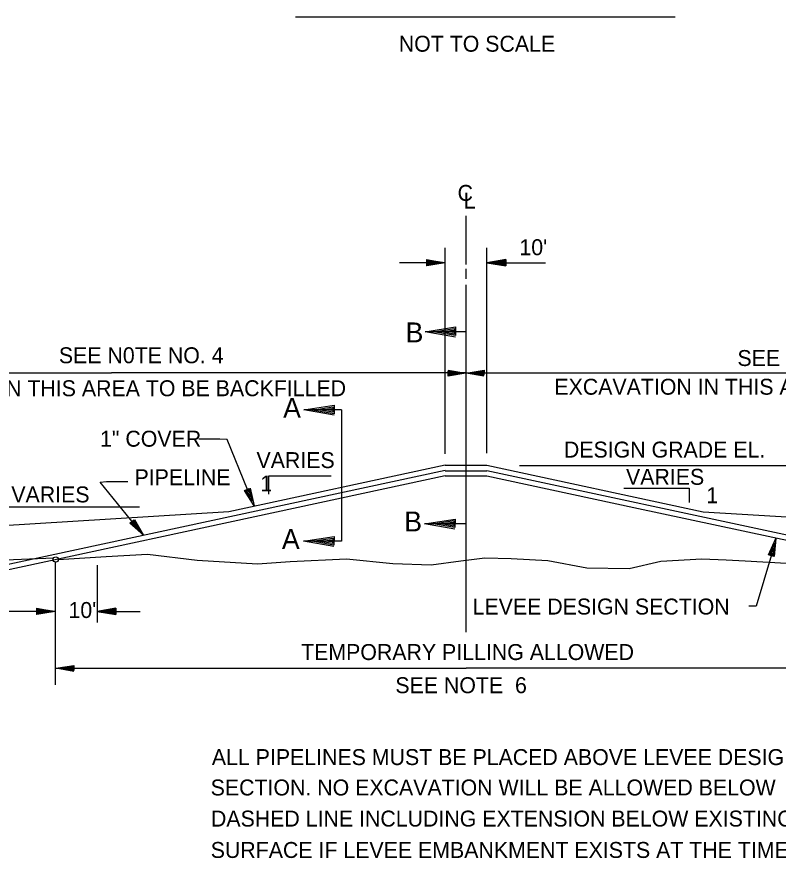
# Model space of a CAD drawing. Extents: x 2127959 to 2137375, y 2146193 to 2153470.
# Drawn here: x 2130277 to 2131850, y 2149874 to 2151610 of the extents above; entities that cross this region are included whole.
import ezdxf

# ---------------------------------------------------------------- set-up
doc = ezdxf.new("R2010")
doc.units = 0
for name, color, linetype in [('Level 1', 7, 'Continuous'), ('Level 3', 7, 'Continuous'), ('Level 5', 7, 'Continuous'), ('Level 50', 7, 'Continuous'), ('Level 63', 7, 'Continuous')]:
    doc.layers.add(name, color=color, linetype=linetype)

msp = doc.modelspace()

# ---------------------------------------------------------------- linework, layer by layer
at = {"layer": 'Level 1'}
for p, q in [((2131205.402, 2151099.111), (2131205.402, 2151199.222)), ((2131205.402, 2151069.227), (2131205.402, 2151090.146)), ((2131205.402, 2150960.045), (2131205.402, 2151057.274)), ((2131162.204, 2150684.43), (2130715.397, 2150588.688)), ((2131162.204, 2150684.43), (2131248.601, 2150684.444)), ((2131248.601, 2150684.444), (2131695.4, 2150588.688)), ((2131162.301, 2150662.426), (2130858.58, 2150597.329)), ((2131162.301, 2150662.426), (2131248.501, 2150662.426)), ((2131248.501, 2150662.426), (2131551.79, 2150597.432)), ((2130715.396, 2150588.701), (2130170.987, 2150554.673)), ((2131695.401, 2150588.702), (2132239.818, 2150554.673)), ((2131836.343, 2150499.825), (2131804.74, 2150393.885)), ((2131804.74, 2150393.885), (2131789.466, 2150393.885))]:
    msp.add_line(p, q, dxfattribs=at)
at = {"layer": 'Level 3'}
for p, q in [((2131162.301, 2150708.371), (2131162.301, 2151133.477)), ((2131248.501, 2150709.475), (2131248.501, 2151133.477)), ((2131123.544, 2151109.078), (2131123.544, 2151096.147)), ((2131123.544, 2151109.078), (2131162.301, 2151102.613)), ((2131287.257, 2151109.078), (2131248.501, 2151102.613)), ((2131286.447, 2151108.283), (2131255.05, 2151103.058)), ((2131286.516, 2151103.526), (2131286.447, 2151108.283)), ((2131287.257, 2151109.078), (2131287.257, 2151096.147)), ((2131162.301, 2151102.613), (2131067.803, 2151102.613)), ((2131162.301, 2151102.613), (2131123.544, 2151102.613)), ((2131162.301, 2151102.613), (2131123.544, 2151096.147)), ((2131124.112, 2151096.94), (2131156.526, 2151102.13)), ((2131124.285, 2151101.975), (2131124.112, 2151096.94)), ((2131124.322, 2151107.938), (2131124.25, 2151103.163)), ((2131124.25, 2151103.163), (2131156.573, 2151103.027)), ((2131156.526, 2151102.13), (2131125.061, 2151101.989)), ((2131125.061, 2151101.989), (2131125.061, 2151097.852)), ((2131125.061, 2151097.852), (2131149.094, 2151101.454)), ((2131125.129, 2151108.009), (2131125.11, 2151103.749)), ((2131125.11, 2151103.749), (2131149.317, 2151103.576)), ((2131156.573, 2151103.027), (2131125.129, 2151108.009)), ((2131149.094, 2151101.454), (2131125.887, 2151101.13)), ((2131125.887, 2151101.13), (2131125.957, 2151098.735)), ((2131125.957, 2151098.735), (2131138.626, 2151100.437)), ((2131149.317, 2151103.576), (2131125.974, 2151107.043)), ((2131125.974, 2151107.043), (2131125.974, 2151104.663)), ((2131125.974, 2151104.663), (2131138.456, 2151104.455)), ((2131138.626, 2151100.437), (2131126.856, 2151100.51)), ((2131126.856, 2151100.51), (2131126.87, 2151099.542)), ((2131126.87, 2151099.542), (2131130.457, 2151099.836)), ((2131138.456, 2151104.455), (2131126.905, 2151106.298)), ((2131126.905, 2151106.298), (2131126.925, 2151105.333)), ((2131126.925, 2151105.333), (2131130.595, 2151105.233)), ((2131248.501, 2151102.613), (2131369.198, 2151102.613)), ((2131248.501, 2151102.613), (2131287.257, 2151102.613)), ((2131248.501, 2151102.613), (2131287.257, 2151096.147)), ((2131255.05, 2151103.058), (2131285.843, 2151103.423)), ((2131286.619, 2151097.025), (2131255.155, 2151102.01)), ((2131255.155, 2151102.01), (2131285.775, 2151102.01)), ((2131285.775, 2151107.474), (2131261.294, 2151103.54)), ((2131261.294, 2151103.54), (2131284.912, 2151104.179)), ((2131285.874, 2151097.82), (2131261.448, 2151101.524)), ((2131261.448, 2151101.524), (2131285.014, 2151101.285)), ((2131284.842, 2151106.529), (2131270.551, 2151104.373)), ((2131270.551, 2151104.373), (2131284.14, 2151104.611)), ((2131284.999, 2151098.713), (2131270.723, 2151100.784)), ((2131270.723, 2151100.784), (2131284.221, 2151100.558)), ((2131284.186, 2151105.784), (2131280.086, 2151105.165)), ((2131284.396, 2151099.423), (2131280.086, 2151099.992)), ((2131284.14, 2151104.611), (2131284.186, 2151105.784)), ((2131284.221, 2151100.558), (2131284.396, 2151099.423)), ((2131284.912, 2151104.179), (2131284.842, 2151106.529)), ((2131285.014, 2151101.285), (2131284.999, 2151098.713)), ((2131285.843, 2151103.423), (2131285.775, 2151107.474)), ((2131285.775, 2151102.01), (2131285.874, 2151097.82)), ((2131286.549, 2151101.989), (2131286.619, 2151097.025)), ((2131205.402, 2150339.898), (2131205.402, 2150925.907)), ((2129739.982, 2150875.068), (2130472.692, 2150875.068)), ((2129739.982, 2150875.068), (2130472.692, 2150875.068)), ((2129739.982, 2150875.068), (2130472.692, 2150875.068)), ((2131205.402, 2150875.068), (2130472.692, 2150875.068)), ((2131205.402, 2150875.068), (2130472.692, 2150875.068)), ((2131205.402, 2150875.068), (2130472.692, 2150875.068)), ((2131205.402, 2150875.068), (2131938.111, 2150875.068)), ((2131315.548, 2150683.978), (2131882.694, 2150683.978)), ((2131162.246, 2150673.424), (2129904.058, 2150403.823)), ((2130797.338, 2150661.771), (2130797.338, 2150624.655)), ((2130926.694, 2150661.771), (2130797.338, 2150661.771)), ((2131162.301, 2150673.203), (2131248.501, 2150673.203)), ((2131248.552, 2150673.424), (2132506.745, 2150403.823)), ((2131531.04, 2150636.975), (2131666.068, 2150636.975)), ((2131666.068, 2150636.975), (2131666.068, 2150607.649)), ((2130858.58, 2150597.329), (2129904.058, 2150392.79)), ((2130531.142, 2150597.738), (2130255.802, 2150597.738)), ((2131551.79, 2150597.432), (2132506.745, 2150392.79)), ((2130356.891, 2150484.697), (2130356.891, 2150231.059)), ((2130443.093, 2150478.437), (2130443.093, 2150360.256)), ((2130356.891, 2150382.98), (2130210.728, 2150382.98)), ((2130318.142, 2150389.445), (2130318.142, 2150376.517)), ((2130318.142, 2150389.445), (2130356.891, 2150382.98)), ((2130356.891, 2150382.98), (2130318.142, 2150382.98)), ((2130356.891, 2150382.98), (2130318.142, 2150376.517)), ((2130318.701, 2150377.31), (2130351.114, 2150382.495)), ((2130318.87, 2150382.343), (2130318.701, 2150377.31)), ((2130318.907, 2150388.308), (2130318.848, 2150383.531)), ((2130318.848, 2150383.531), (2130351.162, 2150383.394)), ((2130319.66, 2150382.363), (2130319.653, 2150378.222)), ((2130319.653, 2150378.222), (2130343.697, 2150381.825)), ((2130351.114, 2150382.495), (2130319.66, 2150382.363)), ((2130319.724, 2150388.359), (2130319.707, 2150384.119)), ((2130319.707, 2150384.119), (2130343.911, 2150383.946)), ((2130351.162, 2150383.394), (2130319.724, 2150388.359)), ((2130343.697, 2150381.825), (2130320.477, 2150381.498)), ((2130320.477, 2150381.498), (2130320.553, 2150379.099)), ((2130320.553, 2150379.099), (2130333.225, 2150380.807)), ((2130343.911, 2150383.946), (2130320.564, 2150387.407)), ((2130320.564, 2150387.407), (2130320.564, 2150385.032)), ((2130320.564, 2150385.032), (2130333.055, 2150384.824)), ((2130333.225, 2150380.807), (2130321.453, 2150380.873)), ((2130321.453, 2150380.873), (2130321.466, 2150379.912)), ((2130321.466, 2150379.912), (2130325.053, 2150380.207)), ((2130333.055, 2150384.824), (2130321.496, 2150386.671)), ((2130321.496, 2150386.671), (2130321.526, 2150385.704)), ((2130321.526, 2150385.704), (2130325.186, 2150385.598)), ((2130481.842, 2150389.445), (2130443.093, 2150382.98)), ((2130443.093, 2150382.98), (2130532.498, 2150382.98)), ((2130443.093, 2150382.98), (2130481.842, 2150382.98)), ((2130443.093, 2150382.98), (2130481.842, 2150376.517)), ((2130481.039, 2150388.652), (2130449.639, 2150383.428)), ((2130449.639, 2150383.428), (2130480.429, 2150383.787)), ((2130481.215, 2150377.393), (2130449.747, 2150382.375)), ((2130449.747, 2150382.375), (2130480.37, 2150382.375)), ((2130480.37, 2150387.84), (2130455.875, 2150383.912)), ((2130455.875, 2150383.912), (2130479.505, 2150384.55)), ((2130480.469, 2150378.185), (2130456.036, 2150381.894)), ((2130456.036, 2150381.894), (2130479.603, 2150381.652)), ((2130479.436, 2150386.892), (2130465.135, 2150384.737)), ((2130465.135, 2150384.737), (2130478.722, 2150384.978)), ((2130479.588, 2150379.085), (2130465.322, 2150381.152)), ((2130465.322, 2150381.152), (2130478.817, 2150380.929)), ((2130478.99, 2150379.79), (2130474.674, 2150380.358)), ((2130478.782, 2150386.15), (2130474.681, 2150385.531)), ((2130478.722, 2150384.978), (2130478.782, 2150386.15)), ((2130478.817, 2150380.929), (2130478.99, 2150379.79)), ((2130479.505, 2150384.55), (2130479.436, 2150386.892)), ((2130479.603, 2150381.652), (2130479.588, 2150379.085)), ((2130480.429, 2150383.787), (2130480.37, 2150387.84)), ((2130480.37, 2150382.375), (2130480.469, 2150378.185)), ((2130481.107, 2150383.891), (2130481.039, 2150388.652)), ((2130481.15, 2150382.363), (2130481.215, 2150377.393)), ((2130481.842, 2150389.445), (2130481.842, 2150376.517)), ((2130356.891, 2150265.559), (2131205.781, 2150265.559)), ((2132054.671, 2150265.559), (2131205.781, 2150265.559))]:
    msp.add_line(p, q, dxfattribs=at)
for points in [[(2130754.087, 2150634.384), (2130711.692, 2150738.053), (2130696.985, 2150738.193), (2130653.196, 2150738.193)], [(2130538.981, 2150539.867), (2130449.295, 2150649.89), (2130462.838, 2150650.805), (2130506.627, 2150650.805)]]:
    msp.add_lwpolyline(points, dxfattribs=at)
msp.add_circle((2130357.753, 2150490.025), 5.388, dxfattribs=at)
at = {"layer": 'Level 5'}
for p, q in [((2130462.183, 2150496.161), (2130547.229, 2150501.301)), ((2130547.229, 2150501.301), (2130649.852, 2150488.438)), ((2130218.267, 2150487.938), (2130286.98, 2150490.803)), ((2130286.98, 2150490.803), (2130353.592, 2150493.438)), ((2130363.138, 2150490.024), (2130462.183, 2150496.161)), ((2130649.852, 2150488.438), (2130774.81, 2150481.147)), ((2130774.81, 2150481.147), (2130842.269, 2150485.748)), ((2130842.269, 2150485.748), (2130958.59, 2150491.283)), ((2130958.59, 2150491.283), (2131053.789, 2150481.54)), ((2131133.25, 2150478.712), (2131194.798, 2150487.231)), ((2131194.798, 2150487.231), (2131243.999, 2150493.714)), ((2131243.999, 2150493.714), (2131298.446, 2150492.368)), ((2131298.446, 2150492.368), (2131374.01, 2150488.042)), ((2131374.01, 2150488.042), (2131455.175, 2150473.025)), ((2131542.239, 2150471.405), (2131608.012, 2150486.42)), ((2131608.012, 2150486.42), (2131692.556, 2150491.144)), ((2131692.556, 2150491.144), (2131742.605, 2150489.127)), ((2131742.605, 2150489.127), (2131781.825, 2150487.367)), ((2131781.825, 2150487.367), (2131867.045, 2150482.766)), ((2131053.789, 2150481.54), (2131133.25, 2150478.712)), ((2131455.175, 2150473.025), (2131542.239, 2150471.405))]:
    msp.add_line(p, q, dxfattribs=at)
at = {"layer": 'Level 50'}
for p, q in [((2131120.956, 2150960.045), (2131120.956, 2150960.045)), ((2131138.423, 2150959.906), (2131138.423, 2150959.906)), ((2131194.843, 2150874.633), (2131194.843, 2150874.633)), ((2131205.127, 2150874.551), (2131205.127, 2150874.551)), ((2131205.453, 2150874.91), (2131205.453, 2150874.91)), ((2131215.733, 2150874.831), (2131215.733, 2150874.831)), ((2130870.25, 2150798.66), (2130870.25, 2150798.66)), ((2130887.717, 2150798.521), (2130887.717, 2150798.521)), ((2130763.872, 2150610.314), (2130763.872, 2150610.314)), ((2130767.822, 2150600.811), (2130767.822, 2150600.811)), ((2131119.749, 2150563.657), (2131119.749, 2150563.657)), ((2131137.216, 2150563.518), (2131137.216, 2150563.518)), ((2130532.445, 2150548.031), (2130532.445, 2150548.031)), ((2130538.883, 2150539.992), (2130538.883, 2150539.992)), ((2130869.734, 2150527.678), (2130869.734, 2150527.678)), ((2130887.201, 2150527.539), (2130887.201, 2150527.539)), ((2131842.755, 2150523.532), (2131842.755, 2150523.532)), ((2131845.5, 2150533.434), (2131845.5, 2150533.434)), ((2130358.062, 2150265.578), (2130358.062, 2150265.578)), ((2130368.344, 2150265.498), (2130368.344, 2150265.498))]:
    msp.add_line(p, q, dxfattribs=at)
for points in [[(2131183.697, 2150949.183), (2131120.956, 2150960.045), (2131183.824, 2150970.009), (2131183.701, 2150952.216), (2131138.423, 2150959.906), (2131181.101, 2150966.665), (2131181.04, 2150955.24), (2131155.212, 2150959.783), (2131178.401, 2150963.324), (2131178.375, 2150958.633), (2131172.68, 2150959.671)], [(2131168.191, 2150880.948), (2131205.127, 2150874.551), (2131168.114, 2150868.685), (2131168.185, 2150879.161), (2131194.843, 2150874.633), (2131169.717, 2150870.652), (2131169.755, 2150877.381), (2131184.96, 2150874.706), (2131171.31, 2150872.618), (2131171.324, 2150875.384), (2131174.676, 2150874.772)], [(2131242.388, 2150868.513), (2131205.453, 2150874.91), (2131242.463, 2150880.776), (2131242.389, 2150870.301), (2131215.733, 2150874.831), (2131240.861, 2150878.809), (2131240.824, 2150872.079), (2131225.616, 2150874.755), (2131239.267, 2150876.844), (2131239.254, 2150874.079), (2131235.904, 2150874.688)], [(2130932.991, 2150787.798), (2130870.25, 2150798.66), (2130933.118, 2150808.624), (2130932.995, 2150790.831), (2130887.717, 2150798.521), (2130930.395, 2150805.28), (2130930.334, 2150793.855), (2130904.506, 2150798.398), (2130927.695, 2150801.939), (2130927.669, 2150797.248), (2130921.974, 2150798.286)], [(2130759.262, 2150637.313), (2130767.822, 2150600.811), (2130747.957, 2150632.584), (2130757.621, 2150636.602), (2130763.872, 2150610.314), (2130750.392, 2150631.863), (2130756.603, 2150634.482), (2130760.073, 2150619.452), (2130752.823, 2150631.191), (2130755.373, 2150632.25), (2130756.133, 2150628.932)], [(2130520.586, 2150572.723), (2130538.883, 2150539.992), (2130511.024, 2150565.061), (2130519.197, 2150571.584), (2130532.445, 2150548.031), (2130513.56, 2150565.039), (2130518.81, 2150569.261), (2130526.289, 2150555.771), (2130516.092, 2150565.061), (2130518.247, 2150566.777), (2130519.881, 2150563.807)], [(2131182.49, 2150552.795), (2131119.749, 2150563.657), (2131182.617, 2150573.621), (2131182.494, 2150555.828), (2131137.216, 2150563.518), (2131179.894, 2150570.277), (2131179.833, 2150558.852), (2131154.005, 2150563.395), (2131177.194, 2150566.936), (2131177.168, 2150562.245), (2131171.473, 2150563.283)], [(2130932.475, 2150516.816), (2130869.734, 2150527.678), (2130932.602, 2150537.642), (2130932.479, 2150519.849), (2130887.201, 2150527.539), (2130929.879, 2150534.298), (2130929.818, 2150522.873), (2130903.99, 2150527.416), (2130927.179, 2150530.957), (2130927.153, 2150526.266), (2130921.458, 2150527.304)], [(2131829.77, 2150499.418), (2131845.5, 2150533.434), (2131841.59, 2150496.162), (2131831.485, 2150498.942), (2131842.755, 2150523.532), (2131840.103, 2150498.223), (2131833.612, 2150499.992), (2131840.13, 2150513.998), (2131838.617, 2150500.275), (2131835.941, 2150501.014), (2131837.398, 2150504.087)], [(2130394.997, 2150259.181), (2130358.062, 2150265.578), (2130395.072, 2150271.446), (2130394.999, 2150260.97), (2130368.344, 2150265.498), (2130393.472, 2150269.476), (2130393.435, 2150262.746), (2130378.225, 2150265.423), (2130391.879, 2150267.511), (2130391.862, 2150264.747), (2130388.512, 2150265.359)]]:
    msp.add_lwpolyline(points, dxfattribs=at)
at = {"layer": 'Level 63'}
for p, q in [((2130853.356, 2151610.191), (2131637.065, 2151610.191)), ((2131205.402, 2150960.045), (2131120.956, 2150960.045)), ((2131205.402, 2150563.657), (2131205.402, 2150960.045)), ((2130948.095, 2150798.66), (2130870.25, 2150798.66)), ((2130948.095, 2150798.66), (2130948.095, 2150527.678)), ((2131205.402, 2150563.657), (2131119.749, 2150563.657)), ((2130948.095, 2150527.678), (2130869.734, 2150527.678))]:
    msp.add_line(p, q, dxfattribs=at)

# ---------------------------------------------------------------- texts
at = {"layer": 'Level 1'}
for s, p in [('NOT TO SCALE', (2131066.434, 2151538.168)), ('C', (2131187.842, 2151230.218)), ('L', (2131200.543, 2151214.519)), ("10'", (2131315.595, 2151118.148)), ('SEE N0TE NO. 4 ', (2130364.267, 2150895.119)), ('SEE N0TE NO. 4 ', (2131765.911, 2150889.419)), ('EXCAVATION IN THIS AREA TO BE BACKFILLED ', (2129946.893, 2150827.068)), ('EXCAVATION IN THIS AREA TO BE BACKFILLED ', (2131387.81, 2150830.14)), ('1" COVER ', (2130449.297, 2150722.881)), (' DESIGN GRADE EL.', (2131395.232, 2150700.406)), ('VARIES', (2130772.504, 2150678.678)), ('PIPELINE', (2130520.562, 2150643.429)), ('VARIES', (2131535.758, 2150644.197)), ('1', (2130780.287, 2150630.484)), ('VARIES', (2130266.104, 2150607.868)), ('1', (2131701.668, 2150606.234)), ("10'", (2130384.192, 2150369.3)), ('LEVEE DESIGN SECTION', (2131218.879, 2150376.453)), ('TEMPORARY PILLING ALLOWED ', (2130864.622, 2150282.539)), ('SEE NOTE  6', (2131059.317, 2150214.087)), ('ALL PIPELINES MUST BE PLACED ABOVE LEVEE DESIGN', (2130680.258, 2150065.69)), ('SECTION. NO EXCAVATION WILL BE ALLOWED BELOW', (2130677.798, 2150002.959)), ('DASHED LINE INCLUDING EXTENSION BELOW EXISTING GROUND', (2130678.443, 2149938.769)), ('SURFACE IF LEVEE EMBANKMENT EXISTS AT THE TIME OF PIPELINE', (2130677.939, 2149873.989))]:
    msp.add_text(s, height=32.931, dxfattribs=at).set_placement(p)
at = {"layer": 'Level 63'}
for s, p in [('B', (2131080.463, 2150938.133)), ('A', (2130827.564, 2150782.54)), ('B', (2131077.668, 2150547.934)), ('A', (2130824.946, 2150511.678))]:
    msp.add_text(s, height=41.164, dxfattribs=at).set_placement(p)

doc.saveas('drawing.dxf')
